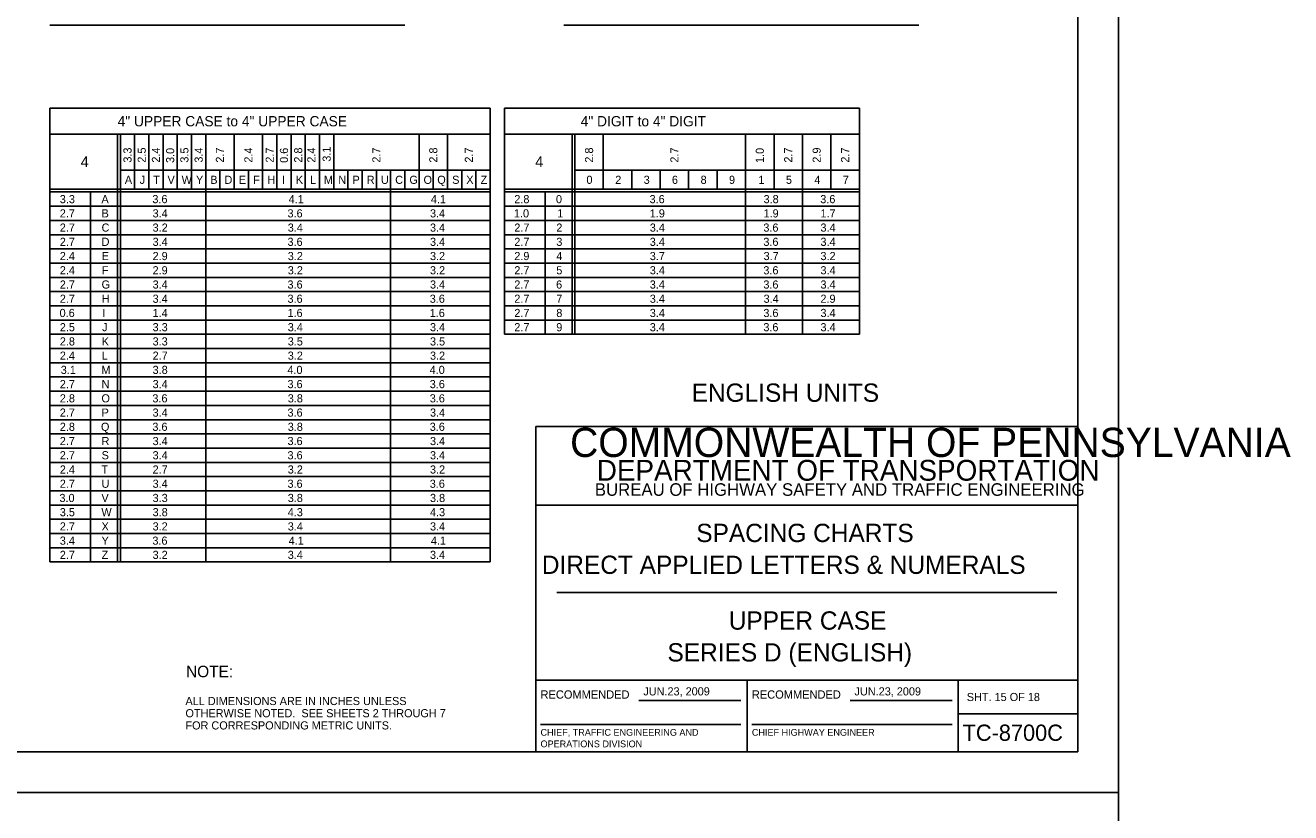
# Model space of a CAD drawing. Extents: x 637580 to 641849, y 297270 to 299646.
# Drawn here: x 640540.8 to 641007.9, y 297856.1 to 298146.6 of the extents above; entities that cross this region are included whole.
import ezdxf

# ---------------------------------------------------------------- set-up
doc = ezdxf.new("R2010")
doc.units = 0
for name, color, linetype in [('1', 7, 'Continuous'), ('2', 7, 'Continuous'), ('XCS-GRID-HVGL', 7, 'Continuous')]:
    doc.layers.add(name, color=color, linetype=linetype)

msp = doc.modelspace()

# ---------------------------------------------------------------- linework, layer by layer
at = {"layer": '1'}
for p, q in [((640929.31, 297878.63), (640929.31, 298442.63)), ((640729.31, 297878.63), (640729.31, 297998.63)), ((640729.31, 297998.63), (640929.31, 297998.63)), ((640929.31, 297969.63), (640729.31, 297969.63)), ((640737.06, 297937.31), (640921.56, 297937.31)), ((640729.31, 297905), (640929.31, 297905)), ((640807.31, 297905), (640807.31, 297878.63)), ((640885.19, 297878.63), (640885.19, 297905)), ((640767.24, 297897.57), (640804.87, 297897.57)), ((640845.24, 297897.57), (640882.87, 297897.57)), ((640730.99, 297888.68), (640804.87, 297888.68)), ((640808.99, 297888.68), (640882.87, 297888.68)), ((640885.19, 297892.63), (640929.31, 297892.63)), ((640929.31, 297878.63), (640143.31, 297878.63)), ((640143.31, 297878.63), (640729.31, 297878.63))]:
    msp.add_line(p, q, dxfattribs=at)
at = {"layer": '2'}
for p, q in [((640549.91, 298146.63), (640680.91, 298146.63)), ((640739.61, 298146.63), (640870.61, 298146.63)), ((640712.41, 298116), (640549.91, 298116)), ((640549.91, 298116), (640549.91, 297948.63)), ((640712.41, 298116), (640712.41, 297948.63)), ((640848.66, 298116), (640717.66, 298116)), ((640717.66, 298116), (640717.66, 298032.63)), ((640848.66, 298032.63), (640848.66, 298116)), ((640549.91, 298106.5), (640712.41, 298106.5)), ((640574.91, 298106.5), (640574.91, 297948.63)), ((640575.91, 298106.5), (640575.91, 297948.63)), ((640581.16, 298106.5), (640581.16, 298086.13)), ((640586.41, 298106.5), (640586.41, 298086.13)), ((640591.66, 298106.5), (640591.66, 298086.13)), ((640596.91, 298106.5), (640596.91, 298086.13)), ((640602.16, 298106.5), (640602.16, 298086.13)), ((640607.41, 298106.5), (640607.41, 297948.63)), ((640617.91, 298106.5), (640617.91, 298086.13)), ((640628.41, 298106.5), (640628.41, 298086.13)), ((640633.66, 298106.5), (640633.66, 298086.13)), ((640638.91, 298106.5), (640638.91, 298086.13)), ((640644.16, 298106.5), (640644.16, 298086.13)), ((640649.41, 298106.5), (640649.41, 298086.13)), ((640654.66, 298106.5), (640654.66, 298086.13)), ((640686.16, 298106.5), (640686.16, 298086.13)), ((640696.66, 298106.5), (640696.66, 298086.13)), ((640717.66, 298106.5), (640848.66, 298106.5)), ((640742.66, 298106.5), (640742.66, 298032.63)), ((640743.66, 298106.5), (640743.66, 298032.63)), ((640754.16, 298106.5), (640754.16, 298086.13)), ((640806.66, 298106.5), (640806.66, 298032.63)), ((640817.16, 298106.5), (640817.16, 298086.13)), ((640827.66, 298106.5), (640827.66, 298032.63)), ((640838.16, 298106.5), (640838.16, 298086.13)), ((640575.91, 298093.13), (640712.41, 298093.13)), ((640612.66, 298093.13), (640612.66, 298086.13)), ((640623.16, 298093.13), (640623.16, 298086.13)), ((640659.91, 298093.13), (640659.91, 298086.13)), ((640665.16, 298093.13), (640665.16, 298086.13)), ((640670.41, 298093.13), (640670.41, 298086.13)), ((640670.41, 298093.13), (640670.41, 298086.13)), ((640675.66, 298093.13), (640675.66, 297948.63)), ((640680.91, 298093.13), (640680.91, 298086.13)), ((640691.41, 298093.13), (640691.41, 298086.13)), ((640701.91, 298093.13), (640701.91, 298086.13)), ((640707.16, 298093.13), (640707.16, 298086.13)), ((640743.66, 298093.13), (640848.66, 298093.13)), ((640764.66, 298093.13), (640764.66, 298086.13)), ((640775.16, 298093.13), (640775.16, 298086.13)), ((640785.66, 298093.13), (640785.66, 298086.13)), ((640796.16, 298093.13), (640796.16, 298086.13)), ((640712.41, 298086.13), (640549.91, 298086.13)), ((640712.41, 298085.13), (640549.91, 298085.13)), ((640564.91, 298085.13), (640564.91, 297948.63)), ((640848.66, 298086.13), (640717.66, 298086.13)), ((640848.66, 298085.13), (640717.66, 298085.13)), ((640732.66, 298085.13), (640732.66, 298032.63)), ((640712.41, 298079.88), (640549.91, 298079.88)), ((640848.66, 298079.88), (640717.66, 298079.88)), ((640712.41, 298074.63), (640549.91, 298074.63)), ((640848.66, 298074.63), (640717.66, 298074.63)), ((640712.41, 298069.38), (640549.91, 298069.38)), ((640848.66, 298069.38), (640717.66, 298069.38)), ((640712.41, 298064.13), (640549.91, 298064.13)), ((640848.66, 298064.13), (640717.66, 298064.13)), ((640712.41, 298058.88), (640549.91, 298058.88)), ((640848.66, 298058.88), (640717.66, 298058.88)), ((640712.41, 298053.63), (640549.91, 298053.63)), ((640848.66, 298053.63), (640717.66, 298053.63)), ((640712.41, 298048.38), (640549.91, 298048.38)), ((640848.66, 298048.38), (640717.66, 298048.38)), ((640712.41, 298043.13), (640549.91, 298043.13)), ((640848.66, 298043.13), (640717.66, 298043.13)), ((640712.41, 298037.88), (640549.91, 298037.88)), ((640848.66, 298037.88), (640717.66, 298037.88)), ((640712.41, 298032.63), (640549.91, 298032.63)), ((640717.66, 298032.63), (640848.66, 298032.63)), ((640712.41, 298027.38), (640549.91, 298027.38)), ((640712.41, 298022.13), (640549.91, 298022.13)), ((640712.41, 298016.88), (640549.91, 298016.88)), ((640712.41, 298011.63), (640549.91, 298011.63)), ((640712.41, 298006.38), (640549.91, 298006.38)), ((640712.41, 298001.13), (640549.91, 298001.13)), ((640712.41, 297995.88), (640549.91, 297995.88)), ((640712.41, 297990.63), (640549.91, 297990.63)), ((640712.41, 297985.38), (640549.91, 297985.38)), ((640712.41, 297980.13), (640549.91, 297980.13)), ((640712.41, 297974.88), (640549.91, 297974.88)), ((640712.41, 297969.63), (640549.91, 297969.63)), ((640712.41, 297964.38), (640549.91, 297964.38)), ((640712.41, 297959.13), (640549.91, 297959.13)), ((640712.41, 297953.88), (640549.91, 297953.88)), ((640549.91, 297948.63), (640549.91, 297948.63)), ((640549.91, 297948.63), (640712.41, 297948.63))]:
    msp.add_line(p, q, dxfattribs=at)
at = {"layer": 'XCS-GRID-HVGL'}
for points in [[(640103.31, 298457.63), (640944.31, 298457.63), (640944.31, 297863.63), (640103.31, 297863.63)], [(640103.31, 297863.63), (640944.31, 297863.63), (640944.31, 297269.63), (640103.31, 297269.63)]]:
    msp.add_lwpolyline(points, close=True, dxfattribs=at)

# ---------------------------------------------------------------- texts
at = {"layer": '1'}
for s, height, p in [('COMMONWEALTH OF PENNSYLVANIA', 10.7828, (640741.9, 297987.36)), ('DEPARTMENT OF TRANSPORTATION', 7.6837, (640751.76, 297978.61)), ('BUREAU OF HIGHWAY SAFETY AND TRAFFIC ENGINEERING', 4.6253, (640751.04, 297973.04)), ('SPACING CHARTS', 6.75, (640788.47, 297955.97)), ('DIRECT APPLIED LETTERS & NUMERALS', 6.75, (640731.47, 297944.22)), ('UPPER CASE', 6.75, (640800.47, 297923.66)), ('SERIES D (ENGLISH)', 6.75, (640777.84, 297911.91)), ('RECOMMENDED', 3.048, (640730.99, 297898.2)), ('RECOMMENDED', 3.048, (640808.99, 297898.2)), ('SHT. 15 OF 18', 3, (640888.32, 297897.31)), ('TC-8700C', 6, (640886.77, 297882.63)), ('CHIEF, TRAFFIC ENGINEERING AND', 2.5, (640730.99, 297884.51)), ('CHIEF HIGHWAY ENGINEER', 2.5, (640808.99, 297884.51)), ('OPERATIONS DIVISION', 2.5, (640730.99, 297880.26))]:
    msp.add_text(s, height=height, dxfattribs=at).set_placement(p)
at = {"layer": '2'}
for s, height, p in [('4" UPPER CASE to 4" UPPER CASE', 3.8, (640574.9, 298109.35)), ('4" DIGIT to 4" DIGIT', 3.8, (640745.81, 298109.35)), ('4', 4, (640561.28, 298094.31)), ('4', 4, (640729.03, 298094.31)), ('A', 3, (640577.56, 298088.13)), ('J', 3, (640583.04, 298088.13)), ('T', 3, (640588.04, 298088.13)), ('V', 3, (640593.31, 298088.13)), ('W', 3, (640598.53, 298088.13)), ('Y', 3, (640603.84, 298088.13)), ('B', 3, (640609.1, 298088.13)), ('D', 3, (640614.35, 298088.13)), ('E', 3, (640619.62, 298088.13)), ('F', 3, (640624.92, 298088.13)), ('H', 3, (640630.19, 298088.13)), ('I', 3, (640635.6, 298088.13)), ('K', 3, (640640.69, 298088.13)), ('L', 3, (640645.94, 298088.13)), ('M', 3, (640651.03, 298088.13)), ('N', 3, (640656.35, 298088.13)), ('P', 3, (640661.6, 298088.13)), ('R', 3, (640666.85, 298088.13)), ('U', 3, (640672.09, 298088.13)), ('C', 3, (640677.35, 298088.13)), ('G', 3, (640682.6, 298088.13)), ('O', 3, (640687.81, 298088.13)), ('Q', 3, (640692.88, 298088.13)), ('S', 3, (640698.37, 298088.13)), ('X', 3, (640703.59, 298088.13)), ('Z', 3, (640708.85, 298088.13)), ('0', 3, (640747.93, 298088.13)), ('2', 3, (640758.56, 298088.13)), ('3', 3, (640769.06, 298088.13)), ('6', 3, (640779.48, 298088.13)), ('8', 3, (640790.06, 298088.13)), ('9', 3, (640800.55, 298088.13)), ('1', 3, (640811.4, 298088.13)), ('5', 3, (640821.56, 298088.13)), ('4', 3, (640832.06, 298088.13)), ('7', 3, (640842.56, 298088.13)), ('3.3', 3, (640553.56, 298081)), ('A', 3, (640568.93, 298081)), ('3.6', 3, (640587.73, 298081)), ('4.1', 3, (640638.03, 298081)), ('4.1', 3, (640690.53, 298081)), ('2.8', 3, (640721.31, 298081)), ('0', 3, (640736.68, 298081)), ('3.6', 3, (640771.23, 298081)), ('3.8', 3, (640813.31, 298081)), ('3.6', 3, (640834.23, 298081)), ('2.7', 3, (640553.56, 298075.75)), ('B', 3, (640568.98, 298075.75)), ('3.4', 3, (640587.81, 298075.75)), ('3.6', 3, (640637.6, 298075.75)), ('3.4', 3, (640690.19, 298075.75)), ('1.0', 3, (640721.18, 298075.75)), ('1', 3, (640737.15, 298075.75)), ('1.9', 3, (640771.3, 298075.75)), ('1.9', 3, (640813.3, 298075.75)), ('1.7', 3, (640834.31, 298075.75)), ('2.7', 3, (640553.56, 298070.5)), ('C', 3, (640568.98, 298070.5)), ('3.2', 3, (640587.81, 298070.5)), ('3.4', 3, (640637.69, 298070.5)), ('3.4', 3, (640690.19, 298070.5)), ('2.7', 3, (640721.31, 298070.5)), ('2', 3, (640736.81, 298070.5)), ('3.4', 3, (640771.31, 298070.5)), ('3.6', 3, (640813.23, 298070.5)), ('3.4', 3, (640834.31, 298070.5)), ('2.7', 3, (640553.56, 298065.25)), ('D', 3, (640568.98, 298065.25)), ('3.4', 3, (640587.81, 298065.25)), ('3.6', 3, (640637.6, 298065.25)), ('3.4', 3, (640690.19, 298065.25)), ('2.7', 3, (640721.31, 298065.25)), ('3', 3, (640736.81, 298065.25)), ('3.4', 3, (640771.31, 298065.25)), ('3.6', 3, (640813.23, 298065.25)), ('3.4', 3, (640834.31, 298065.25)), ('2.4', 3, (640553.56, 298060)), ('E', 3, (640568.99, 298060)), ('2.9', 3, (640587.8, 298060)), ('3.2', 3, (640637.69, 298060)), ('3.2', 3, (640690.19, 298060)), ('2.9', 3, (640721.3, 298060)), ('4', 3, (640736.81, 298060)), ('3.7', 3, (640771.31, 298060)), ('3.7', 3, (640813.31, 298060)), ('3.2', 3, (640834.31, 298060)), ('2.4', 3, (640553.56, 298054.75)), ('F', 3, (640569.05, 298054.75)), ('2.9', 3, (640587.8, 298054.75)), ('3.2', 3, (640637.69, 298054.75)), ('3.2', 3, (640690.19, 298054.75)), ('2.7', 3, (640721.31, 298054.75)), ('5', 3, (640736.81, 298054.75)), ('3.4', 3, (640771.31, 298054.75)), ('3.6', 3, (640813.23, 298054.75)), ('3.4', 3, (640834.31, 298054.75)), ('2.7', 3, (640553.56, 298049.5)), ('G', 3, (640568.98, 298049.5)), ('3.4', 3, (640587.81, 298049.5)), ('3.6', 3, (640637.6, 298049.5)), ('3.4', 3, (640690.19, 298049.5)), ('2.7', 3, (640721.31, 298049.5)), ('6', 3, (640736.73, 298049.5)), ('3.4', 3, (640771.31, 298049.5)), ('3.6', 3, (640813.23, 298049.5)), ('3.4', 3, (640834.31, 298049.5)), ('2.7', 3, (640553.56, 298044.25)), ('H', 3, (640569.06, 298044.25)), ('3.4', 3, (640587.81, 298044.25)), ('3.6', 3, (640637.6, 298044.25)), ('3.6', 3, (640690.1, 298044.25)), ('2.7', 3, (640721.31, 298044.25)), ('7', 3, (640736.81, 298044.25)), ('3.4', 3, (640771.31, 298044.25)), ('3.4', 3, (640813.31, 298044.25)), ('2.9', 3, (640834.3, 298044.25)), ('0.6', 3, (640553.48, 298039)), ('I', 3, (640569.23, 298039)), ('1.4', 3, (640587.81, 298039)), ('1.6', 3, (640637.6, 298039)), ('1.6', 3, (640690.1, 298039)), ('2.7', 3, (640721.31, 298039)), ('8', 3, (640736.81, 298039)), ('3.4', 3, (640771.31, 298039)), ('3.6', 3, (640813.23, 298039)), ('3.4', 3, (640834.31, 298039)), ('2.5', 3, (640553.56, 298033.75)), ('J', 3, (640569.17, 298033.75)), ('3.3', 3, (640587.81, 298033.75)), ('3.4', 3, (640637.69, 298033.75)), ('3.4', 3, (640690.19, 298033.75)), ('2.7', 3, (640721.31, 298033.75)), ('9', 3, (640736.8, 298033.75)), ('3.4', 3, (640771.31, 298033.75)), ('3.6', 3, (640813.23, 298033.75)), ('3.4', 3, (640834.31, 298033.75)), ('2.8', 3, (640553.56, 298028.5)), ('K', 3, (640569.06, 298028.5)), ('3.3', 3, (640587.81, 298028.5)), ('3.5', 3, (640637.69, 298028.5)), ('3.5', 3, (640690.19, 298028.5)), ('2.4', 3, (640553.56, 298023.25)), ('L', 3, (640569.06, 298023.25)), ('2.7', 3, (640587.81, 298023.25)), ('3.2', 3, (640637.69, 298023.25)), ('3.2', 3, (640690.19, 298023.25)), ('3.1', 3, (640553.9, 298018)), ('M', 3, (640568.91, 298018)), ('3.8', 3, (640587.81, 298018)), ('4.0', 3, (640637.56, 298018)), ('4.0', 3, (640690.06, 298018)), ('2.7', 3, (640553.56, 298012.75)), ('N', 3, (640568.98, 298012.75)), ('3.4', 3, (640587.81, 298012.75)), ('3.6', 3, (640637.6, 298012.75)), ('3.6', 3, (640690.1, 298012.75)), ('ENGLISH UNITS', 6.75, (640786.74, 298007.72)), ('2.8', 3, (640553.56, 298007.5)), ('O', 3, (640568.93, 298007.5)), ('3.6', 3, (640587.73, 298007.5)), ('3.8', 3, (640637.69, 298007.5)), ('3.6', 3, (640690.1, 298007.5)), ('2.7', 3, (640553.56, 298002.25)), ('P', 3, (640568.98, 298002.25)), ('3.4', 3, (640587.81, 298002.25)), ('3.6', 3, (640637.6, 298002.25)), ('3.4', 3, (640690.19, 298002.25)), ('2.8', 3, (640553.56, 297997)), ('Q', 3, (640568.75, 297997)), ('3.6', 3, (640587.73, 297997)), ('3.8', 3, (640637.69, 297997)), ('3.6', 3, (640690.1, 297997)), ('2.7', 3, (640553.56, 297991.75)), ('R', 3, (640568.98, 297991.75)), ('3.4', 3, (640587.81, 297991.75)), ('3.6', 3, (640637.6, 297991.75)), ('3.4', 3, (640690.19, 297991.75)), ('2.7', 3, (640553.56, 297986.5)), ('S', 3, (640568.99, 297986.5)), ('3.4', 3, (640587.81, 297986.5)), ('3.6', 3, (640637.6, 297986.5)), ('3.4', 3, (640690.19, 297986.5)), ('2.4', 3, (640553.56, 297981.25)), ('T', 3, (640568.92, 297981.25)), ('2.7', 3, (640587.81, 297981.25)), ('3.2', 3, (640637.69, 297981.25)), ('3.2', 3, (640690.19, 297981.25)), ('2.7', 3, (640553.56, 297976)), ('U', 3, (640568.97, 297976)), ('3.4', 3, (640587.81, 297976)), ('3.6', 3, (640637.6, 297976)), ('3.6', 3, (640690.1, 297976)), ('3.0', 3, (640553.43, 297970.75)), ('V', 3, (640568.93, 297970.75)), ('3.3', 3, (640587.81, 297970.75)), ('3.8', 3, (640637.69, 297970.75)), ('3.8', 3, (640690.19, 297970.75)), ('3.5', 3, (640553.56, 297965.5)), ('W', 3, (640568.91, 297965.5)), ('3.8', 3, (640587.81, 297965.5)), ('4.3', 3, (640637.69, 297965.5)), ('4.3', 3, (640690.19, 297965.5)), ('2.7', 3, (640553.56, 297960.25)), ('X', 3, (640568.97, 297960.25)), ('3.2', 3, (640587.81, 297960.25)), ('3.4', 3, (640637.69, 297960.25)), ('3.4', 3, (640690.19, 297960.25)), ('3.4', 3, (640553.56, 297955)), ('Y', 3, (640568.97, 297955)), ('3.6', 3, (640587.73, 297955)), ('4.1', 3, (640638.03, 297955)), ('4.1', 3, (640690.53, 297955)), ('2.7', 3, (640553.56, 297949.75)), ('Z', 3, (640568.98, 297949.75)), ('3.2', 3, (640587.81, 297949.75)), ('3.4', 3, (640637.69, 297949.75)), ('3.4', 3, (640690.19, 297949.75)), ('NOTE:', 4.25, (640600.16, 297906.1)), ('JUN.23, 2009', 3, (640768.93, 297899.39)), ('ALL DIMENSIONS ARE IN INCHES UNLESS', 3, (640599.94, 297895.83)), ('OTHERWISE NOTED.  SEE SHEETS 2 THROUGH 7', 3, (640599.94, 297891.33)), ('FOR CORRESPONDING METRIC UNITS.', 3, (640599.94, 297886.83))]:
    msp.add_text(s, height=height, dxfattribs=at).set_placement(p)
for s, rotation, p in [('3.3', 90, (640580.04, 298095.96)), ('2.5', 90, (640585.29, 298095.96)), ('2.4', 90, (640590.54, 298095.96)), ('3.0', 90, (640595.79, 298095.83)), ('3.5', 90, (640601.04, 298095.96)), ('3.4', 90, (640606.29, 298095.96)), ('2.7', 90, (640614.16, 298095.96)), ('2.4', 90, (640624.66, 298095.96)), ('2.7', 90, (640632.54, 298095.96)), ('0.6', 90, (640637.79, 298095.88)), ('2.8', 90, (640643.04, 298095.96)), ('2.4', 90, (640647.9, 298095.96)), ('3.1', 90, (640653.54, 298096.31)), ('2.7', 90, (640671.91, 298095.96)), ('2.8', 90, (640692.91, 298095.96)), ('2.7', 90, (640706.04, 298095.96)), ('2.8', 90, (640750.41, 298095.96)), ('2.7', 90, (640781.91, 298095.96)), ('1.0', 90, (640813.41, 298095.83)), ('2.7', 90, (640823.91, 298095.96)), ('2.9', 90, (640834.41, 298095.95)), ('2.7', 90, (640844.91, 298095.96)), ('JUN.23, 2009', 360, (640846.88, 297899.39))]:
    msp.add_text(s, height=3, rotation=rotation, dxfattribs=at).set_placement(p)

doc.saveas('drawing.dxf')
